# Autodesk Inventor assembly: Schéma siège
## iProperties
Shininess: 64.0
Length Units: 11269
Angle Units: 11279
Time Units: 11290
Mass Units: 11283
Length Display Precision: 3
Angle Display Precision: 2
Compacted: True
Created: 2004-06
Part Number: Schéma siège
Document SubType Name: Assembly
Designer: administrateur
Density: 0.0
Volumn: 0.0
Area: 0.0
PropertySet Name: Model Information
Control State: 0
Master: False
Checked Out: False
Author: administrateur
